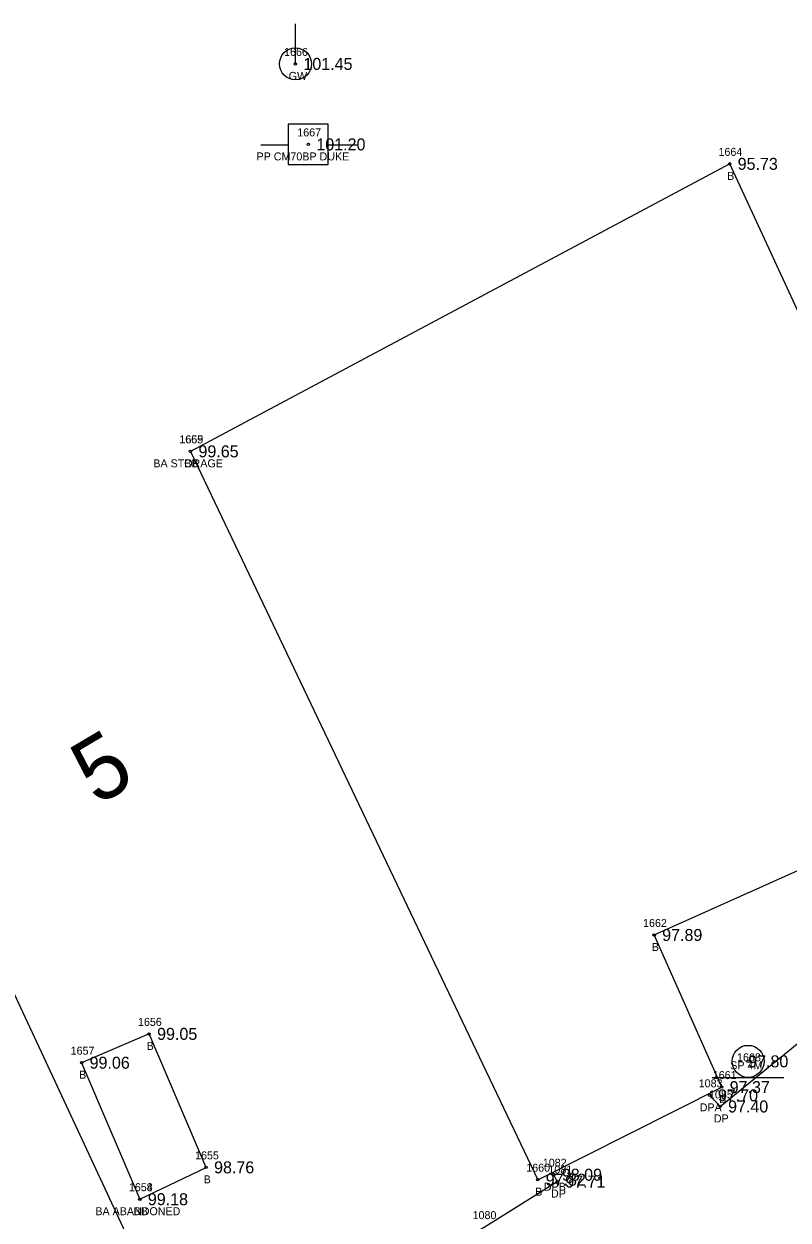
# Model space of a CAD drawing. Extents: x 2529517 to 2532038, y 935000 to 936944.
# Drawn here: x 2530749.4 to 2530845, y 935818.5 to 935968 of the extents above; entities that cross this region are included whole.
import ezdxf

# ---------------------------------------------------------------- set-up
doc = ezdxf.new("R2010")
doc.units = 0
for name, color, linetype in [('RD_EX_Bldg', 7, 'Continuous'), ('RD_EX_Bldg_txCode', 7, 'Continuous'), ('RD_EX_BldgApp', 7, 'Continuous'), ('RD_EX_BldgApp_txCode', 7, 'Continuous'), ('RD_EX_Driveway', 7, 'Continuous'), ('RD_EX_Driveway_txCode', 7, 'Continuous'), ('RD_EX_TX_Bldg_ELEV', 7, 'Continuous'), ('RD_EX_TX_BldgApp_ELEV', 7, 'Continuous'), ('RD_EX_TX_Driveway_ELEV', 7, 'Continuous'), ('RD_EX_TX_UT_ELEV', 7, 'Continuous'), ('RD_EX_UT', 7, 'Continuous'), ('RD_EX_UT_txCode', 7, 'Continuous'), ('RD_HC_Survey_ELEV', 7, 'Continuous'), ('RD_HC_TX_Sta50', 7, 'Continuous'), ('RD_SMD_Locator', 7, 'Continuous')]:
    doc.layers.add(name, color=color, linetype=linetype)

msp = doc.modelspace()

# ---------------------------------------------------------------- linework, layer by layer
at = {"layer": 'RD_EX_Bldg'}
for points in [[(2530770.25, 935914.58), (2530813.66, 935823.56), (2530836.66, 935835.13), (2530828.22, 935854.14), (2530872.98, 935874.21), (2530837.66, 935950.51), (2530770.25, 935914.58)], [(2530713.74, 935846.97), (2530751.17, 935770.08), (2530778.04, 935782.8), (2530741.92, 935860.25), (2530713.74, 935846.97)], [(2530763.92, 935821.12), (2530772.2, 935825.1), (2530765.08, 935841.78), (2530756.64, 935838.18), (2530763.92, 935821.12)]]:
    msp.add_lwpolyline(points, dxfattribs=at)
at = {"layer": 'RD_EX_BldgApp'}
msp.add_line((2530835.45, 935836.32), (2530844.45, 935836.32), dxfattribs=at)
msp.add_circle((2530839.97, 935838.35), 2, dxfattribs=at)
at = {"layer": 'RD_EX_Driveway'}
for points in [[(2530835.18, 935834.1), (2530836.46, 935832.71), (2530846.32, 935840.72), (2530852.09, 935850.74), (2530868.32, 935858.23), (2530887.31, 935854.07), (2530913.36, 935866.89), (2530921.11, 935858.25), (2530924.84, 935856.95)], [(2530775.85, 935769.27), (2530781.83, 935782.56), (2530782.59, 935791.64), (2530778.02, 935800.99), (2530806.95, 935817.63), (2530816.1, 935823.33), (2530815.68, 935824.18)]]:
    msp.add_lwpolyline(points, dxfattribs=at)
at = {"layer": 'RD_EX_UT'}
for p, q in [((2530783.37, 935963), (2530783.37, 935968)), ((2530787.48, 935955.45), (2530782.48, 935955.45)), ((2530782.48, 935955.45), (2530782.48, 935950.45)), ((2530787.48, 935950.45), (2530787.48, 935955.45)), ((2530779.05, 935952.88), (2530782.52, 935952.88)), ((2530787.41, 935952.88), (2530791.05, 935952.88)), ((2530782.48, 935950.45), (2530787.48, 935950.45))]:
    msp.add_line(p, q, dxfattribs=at)
msp.add_circle((2530783.37, 935963), 2, dxfattribs=at)
at = {"layer": 'RD_SMD_Locator'}
for centre in [(2530783.37, 935963), (2530784.99, 935952.94), (2530837.66, 935950.51), (2530770.25, 935914.58), (2530770.25, 935914.58), (2530828.22, 935854.14), (2530765.08, 935841.78), (2530756.64, 935838.18), (2530839.97, 935838.35), (2530836.66, 935835.13), (2530835.18, 935834.1), (2530836.46, 935832.71), (2530772.2, 935825.1), (2530815.68, 935824.18), (2530813.66, 935823.56), (2530816.1, 935823.33), (2530763.92, 935821.12), (2530763.92, 935821.12)]:
    msp.add_circle(centre, 0.15, dxfattribs=at)

# ---------------------------------------------------------------- texts
at = {"layer": 'RD_EX_Bldg_txCode'}
for s, p in [('1664', (2530836.26, 935951.51)), ('B', (2530837.35, 935948.51)), ('1665', (2530768.85, 935915.58)), ('1659', (2530768.88, 935915.58)), ('BA STORAGE', (2530765.61, 935912.58)), ('BB', (2530769.47, 935912.58)), ('1662', (2530826.83, 935855.14)), ('B', (2530827.92, 935852.14)), ('1656', (2530763.69, 935842.78)), ('B', (2530764.77, 935839.78)), ('1657', (2530755.27, 935839.18)), ('B', (2530756.33, 935836.18)), ('1661', (2530835.55, 935836.13)), ('B', (2530836.35, 935833.13)), ('1655', (2530770.83, 935826.1)), ('1660', (2530812.23, 935824.56)), ('B', (2530771.9, 935823.1)), ('1654', (2530762.55, 935822.12)), ('1658', (2530762.55, 935822.12)), ('B', (2530813.35, 935821.56)), ('BA ABANDONED', (2530758.36, 935819.12)), ('BB', (2530763.14, 935819.12))]:
    msp.add_text(s, height=1, dxfattribs=at).set_placement(p)
at = {"layer": 'RD_EX_BldgApp_txCode'}
for s, p in [('1668', (2530838.58, 935838.35)), ('SP 4M', (2530837.73, 935837.35))]:
    msp.add_text(s, height=1, dxfattribs=at).set_placement(p)
at = {"layer": 'RD_EX_Driveway_txCode'}
for s, p in [('1083', (2530833.79, 935835.1)), ('1085', (2530835.07, 935833.71)), ('DPA', (2530833.91, 935832.1)), ('DP', (2530835.68, 935830.71)), ('1082', (2530814.3, 935825.18)), ('1081', (2530815, 935824.33)), ('DPB', (2530814.43, 935822.18)), ('DP', (2530815.32, 935821.33)), ('1080', (2530805.52, 935818.63))]:
    msp.add_text(s, height=1, dxfattribs=at).set_placement(p)
at = {"layer": 'RD_EX_TX_Bldg_ELEV'}
for s, p in [('95.73', (2530838.66, 935949.76)), ('99.65', (2530771.25, 935913.83)), ('99.65', (2530771.25, 935913.83)), ('97.89', (2530829.22, 935853.39)), ('99.05', (2530766.08, 935841.03)), ('99.06', (2530757.64, 935837.43)), ('97.37', (2530837.66, 935834.38)), ('98.76', (2530773.2, 935824.35)), ('97.82', (2530814.66, 935822.81)), ('99.18', (2530764.92, 935820.37)), ('99.18', (2530764.92, 935820.37))]:
    msp.add_text(s, height=1.5, dxfattribs=at).set_placement(p)
at = {"layer": 'RD_EX_TX_BldgApp_ELEV'}
msp.add_text('97.80', height=1.5, dxfattribs=at).set_placement((2530839.97, 935837.6))
at = {"layer": 'RD_EX_TX_Driveway_ELEV'}
for s, p in [('97.70', (2530836.18, 935833.35)), ('97.40', (2530837.46, 935831.96)), ('98.09', (2530816.68, 935823.43)), ('97.71', (2530817.1, 935822.58))]:
    msp.add_text(s, height=1.5, dxfattribs=at).set_placement(p)
at = {"layer": 'RD_EX_TX_UT_ELEV'}
msp.add_text('101.45', height=1.5, dxfattribs=at).set_placement((2530784.37, 935962.25))
at = {"layer": 'RD_EX_UT_txCode'}
for s, p in [('1666', (2530781.95, 935964)), ('GW', (2530782.53, 935961)), ('1667', (2530783.6, 935953.94)), ('PP CM70BP DUKE', (2530778.51, 935950.94))]:
    msp.add_text(s, height=1, dxfattribs=at).set_placement(p)
at = {"layer": 'RD_HC_Survey_ELEV'}
msp.add_text('101.20', height=1.5, dxfattribs=at).set_placement((2530785.99, 935952.19))
at = {"layer": 'RD_HC_TX_Sta50'}
msp.add_text('5', height=8, rotation=30.6357, dxfattribs=at).set_placement((2530758.56, 935870.21))

doc.saveas('drawing.dxf')
